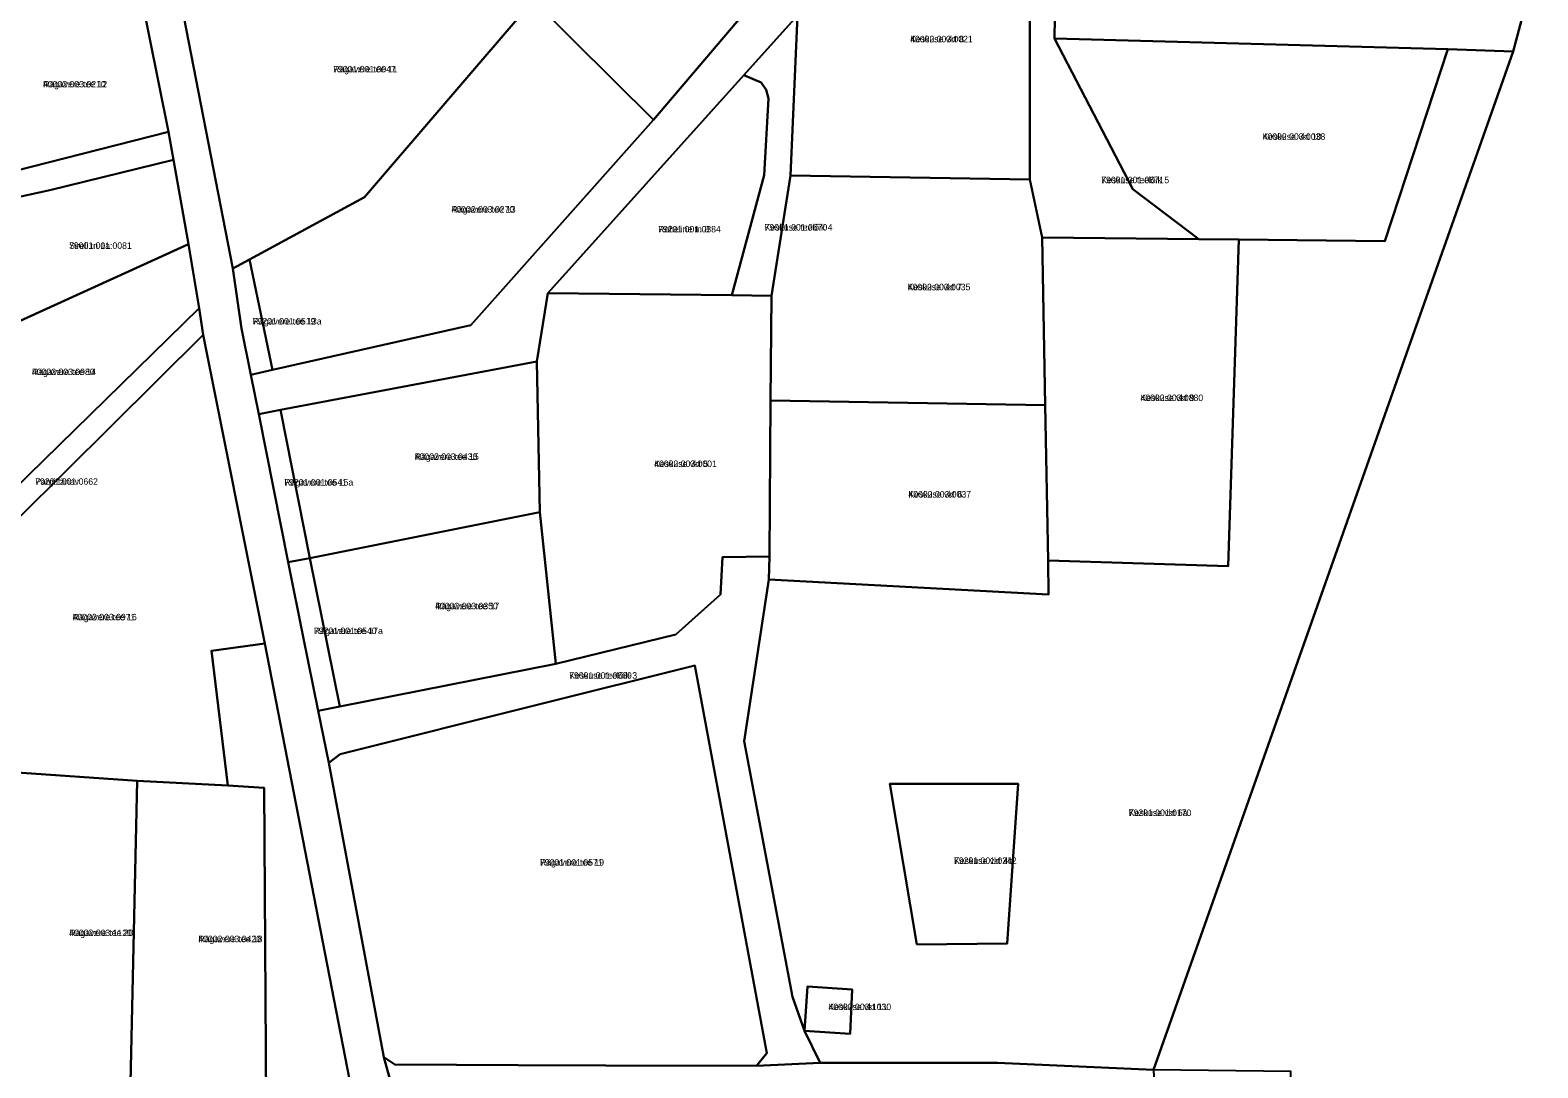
# Model space of a CAD drawing. Extents: x 587616 to 632239, y 6547421 to 6574977.
# Drawn here: x 603991.3 to 604340.3, y 6569303.6 to 6569543.9 of the extents above; entities that cross this region are included whole.
import ezdxf

# ---------------------------------------------------------------- set-up
doc = ezdxf.new("R2010")
doc.units = 0
for name, color, linetype in [('L_AADRESS', 7, 'Continuous'), ('PIIR', 7, 'Continuous'), ('TUNNUS', 7, 'Continuous')]:
    doc.layers.add(name, color=color, linetype=linetype)

msp = doc.modelspace()

# ---------------------------------------------------------------- linework, layer by layer
at = {"layer": 'PIIR'}
for points in [[(603982.29, 6569732.31), (603991.72, 6569734.34), (603999.57, 6569736.03), (603992.82, 6569727.43), (603996.82, 6569702.19), (604003.22, 6569669.18), (604004.94, 6569661.89), (604011.11, 6569629.43), (604017.79, 6569595.04), (604018.7, 6569588.68), (604025.25, 6569555.77), (604038.27, 6569488.72), (604040.3, 6569474.82), (604042.44, 6569464.1), (604044.26, 6569454.94), (604051.09, 6569420.69), (604054.53, 6569403.44), (604058.03, 6569386.3), (604060.49, 6569374.22), (604073.19, 6569306.11), (604076.71, 6569293.52)], [(604069.43, 6569279.45), (604045.67, 6569401.88), (604031.42, 6569473.35), (604030.48, 6569479.48), (604027.98, 6569494.3), (604024.51, 6569513.82), (604023.35, 6569520.32), (604016.54, 6569554.1), (604009.88, 6569586.85), (604008.39, 6569592.82), (604001.97, 6569626.48), (603995.19, 6569660.95), (603994, 6569667.82), (603987.46, 6569701.73)], [(604168.95, 6569547.25), (604156.51, 6569533.42), (604111.2, 6569483.01), (604108.65, 6569467.12), (604049.32, 6569455.96), (604044.26, 6569454.94), (604042.44, 6569464.1), (604047.45, 6569465.21), (604093.34, 6569475.55), (604135.66, 6569523.13), (604156.33, 6569547.41)]]:
    msp.add_lwpolyline(points, dxfattribs=at)
for points in [[(604256.56, 6569639.11), (604352.31, 6569665.54), (604360.92, 6569638.11), (604334.64, 6569538.95), (604319.53, 6569539.5), (604228.48, 6569541.95), (604229.44, 6569604.23), (604250.45, 6569622.25), (604254.82, 6569629.57)], [(604360.92, 6569638.11), (604431.51, 6569646.89), (604362.29, 6569373.98), (604343.36, 6569297.94), (604283.29, 6569296.75), (604283.18, 6569302.74), (604251.37, 6569303.14), (604334.64, 6569538.95)], [(604216.65, 6569593.17), (604229.44, 6569604.23), (604228.48, 6569541.95), (604234.54, 6569530.24), (604246.61, 6569507.02), (604261.9, 6569495.47), (604225.63, 6569495.88), (604222.76, 6569509.28), (604222.68, 6569588.48)], [(604216.65, 6569593.17), (604222.68, 6569588.48), (604222.76, 6569509.28), (604167.31, 6569510.23), (604168.95, 6569547.25)], [(604038.27, 6569488.72), (604025.25, 6569555.77), (604062.72, 6569563.1), (604094.43, 6569568.97), (604115.49, 6569573.57), (604129.54, 6569579.47), (604131.26, 6569576.68), (604107.75, 6569550.7), (604068.73, 6569505.19), (604042.12, 6569490.8)], [(604135.66, 6569523.13), (604107.75, 6569550.7), (604131.26, 6569576.68), (604156.33, 6569547.41)], [(603965.12, 6569543.33), (603973.78, 6569545.1), (604016.54, 6569554.1), (604023.35, 6569520.32), (603971.54, 6569507.11)], [(604042.12, 6569490.8), (604068.73, 6569505.19), (604107.75, 6569550.7), (604135.66, 6569523.13), (604093.34, 6569475.55), (604047.45, 6569465.21)], [(604156.51, 6569533.42), (604168.95, 6569547.25), (604167.31, 6569510.23), (604162.93, 6569482.38), (604153.76, 6569482.49), (604161.23, 6569510.31), (604162.22, 6569528.02), (604161.7, 6569530.08), (604160.55, 6569531.75)], [(604228.48, 6569541.95), (604319.53, 6569539.5), (604304.93, 6569495), (604271.1, 6569495.37), (604261.9, 6569495.47), (604246.61, 6569507.02), (604234.54, 6569530.24)], [(604162.33, 6569416.66), (604227.1, 6569413.22), (604226.97, 6569421.06), (604268.63, 6569419.74), (604271.1, 6569495.37), (604304.93, 6569495), (604319.53, 6569539.5), (604334.64, 6569538.95), (604251.37, 6569303.14), (604215.24, 6569304.78), (604174.21, 6569304.8), (604170.57, 6569312.18), (604167.82, 6569320.05), (604156.65, 6569379.28)], [(604161.23, 6569510.31), (604153.76, 6569482.49), (604111.2, 6569483.01), (604156.51, 6569533.42), (604160.55, 6569531.75), (604161.7, 6569530.08), (604162.22, 6569528.02)], [(603862.88, 6569483.6), (603861.57, 6569489.5), (603912.48, 6569499.04), (603920.87, 6569500.75), (603923.88, 6569499.22), (603971.54, 6569507.11), (604023.35, 6569520.32), (604024.51, 6569513.82), (603995.92, 6569506.83), (603972.91, 6569501.79), (603923.99, 6569491.28), (603913.66, 6569492.89)], [(604024.51, 6569513.82), (604027.98, 6569494.3), (603980.33, 6569472.63), (603972.91, 6569501.79), (603995.92, 6569506.83)], [(604167.31, 6569510.23), (604222.76, 6569509.28), (604225.63, 6569495.88), (604226.29, 6569457.08), (604162.69, 6569458.11), (604162.93, 6569482.38)], [(604271.1, 6569495.37), (604268.63, 6569419.74), (604226.97, 6569421.06), (604226.29, 6569457.08), (604225.63, 6569495.88), (604261.9, 6569495.47)], [(603967.48, 6569466.85), (603980.33, 6569472.63), (604027.98, 6569494.3), (604030.48, 6569479.48), (603983.65, 6569433.72)], [(604040.3, 6569474.82), (604038.27, 6569488.72), (604042.12, 6569490.8), (604047.45, 6569465.21), (604042.44, 6569464.1)], [(604162.93, 6569482.38), (604162.69, 6569458.11), (604162.52, 6569422.03), (604151.61, 6569421.88), (604151.14, 6569413.22), (604140.82, 6569403.98), (604113.03, 6569397.15), (604109.36, 6569432.26), (604108.65, 6569467.12), (604111.2, 6569483.01), (604153.76, 6569482.49)], [(604031.42, 6569473.35), (603956.71, 6569399.26), (603944.7, 6569397.73), (603938.22, 6569400.57), (603943.12, 6569404.71), (603947.64, 6569404.3), (603983.65, 6569433.72), (604030.48, 6569479.48)], [(604045.67, 6569401.88), (604033.32, 6569400.14), (604037.09, 6569368.95), (604016.12, 6569370.08), (603987.18, 6569372.04), (603987.59, 6569381.47), (603956.71, 6569399.26), (604031.42, 6569473.35)], [(604049.32, 6569455.96), (604108.65, 6569467.12), (604109.36, 6569432.26), (604056.1, 6569421.64)], [(604162.69, 6569458.11), (604226.29, 6569457.08), (604226.97, 6569421.06), (604227.1, 6569413.22), (604162.33, 6569416.66), (604162.52, 6569422.03)], [(604044.26, 6569454.94), (604049.32, 6569455.96), (604056.1, 6569421.64), (604051.09, 6569420.69)], [(604056.1, 6569421.64), (604109.36, 6569432.26), (604113.03, 6569397.15), (604062.99, 6569387.31)], [(604174.21, 6569304.8), (604159.51, 6569304.09), (604161.89, 6569307.03), (604153.05, 6569354.41), (604145.2, 6569396.79), (604109.33, 6569387.8), (604063.07, 6569376.21), (604060.49, 6569374.22), (604058.03, 6569386.3), (604062.99, 6569387.31), (604113.03, 6569397.15), (604140.82, 6569403.98), (604151.14, 6569413.22), (604151.61, 6569421.88), (604162.52, 6569422.03), (604162.33, 6569416.66), (604156.65, 6569379.28), (604167.82, 6569320.05), (604170.57, 6569312.18)], [(604051.09, 6569420.69), (604056.1, 6569421.64), (604062.99, 6569387.31), (604058.03, 6569386.3), (604054.53, 6569403.44)], [(604046.01, 6569295.5), (604045.51, 6569368.48), (604037.09, 6569368.95), (604033.32, 6569400.14), (604045.67, 6569401.88), (604069.43, 6569279.45), (604065.21, 6569279), (604050.67, 6569277.94), (604045.83, 6569283.07), (603983.91, 6569284.72), (603984.67, 6569297.56), (604014.53, 6569296.7)], [(604060.49, 6569374.22), (604063.07, 6569376.22), (604109.33, 6569387.8), (604145.2, 6569396.79), (604153.05, 6569354.41), (604161.89, 6569307.03), (604159.51, 6569304.09), (604124.58, 6569304.17), (604104.31, 6569304.25), (604075.76, 6569304.36), (604073.19, 6569306.11)], [(603985.01, 6569307.79), (603986.99, 6569364.95), (603987.18, 6569372.04), (604016.12, 6569370.08), (604014.53, 6569296.7), (603984.67, 6569297.56)], [(604016.12, 6569370.08), (604037.09, 6569368.95), (604045.51, 6569368.48), (604046.01, 6569295.5), (604014.53, 6569296.7)], [(604196.62, 6569332.15), (604217.54, 6569332.43), (604220.02, 6569369.38), (604190.37, 6569369.4)], [(604196.62, 6569332.15), (604190.37, 6569369.4), (604220.02, 6569369.38), (604217.54, 6569332.43)], [(604181.13, 6569311.51), (604170.57, 6569312.18), (604171.25, 6569322.47), (604181.65, 6569321.79)], [(604170.57, 6569312.18), (604181.13, 6569311.51), (604181.65, 6569321.79), (604171.25, 6569322.47)], [(604253.8, 6569253.12), (604244.02, 6569253), (604246.39, 6569256.14), (604244.76, 6569291.48), (604241.79, 6569295.12), (604235.71, 6569297.44), (604197.35, 6569298.13), (604185.57, 6569298.31), (604167.39, 6569298.13), (604119.65, 6569297.8), (604081.31, 6569296.76), (604076.71, 6569293.52), (604073.19, 6569306.11), (604075.76, 6569304.36), (604104.31, 6569304.25), (604124.58, 6569304.17), (604159.51, 6569304.09), (604174.21, 6569304.8), (604215.25, 6569304.78), (604251.37, 6569303.14), (604253.45, 6569259.81), (604257.68, 6569253.23)]]:
    msp.add_lwpolyline(points, close=True, dxfattribs=at)

# ---------------------------------------------------------------- texts
at = {"layer": 'L_AADRESS'}
for s, p in [('Keskuse vkt 8', (604195.04, 6569541.06)), ('Rägavere tee 11', (604061.49, 6569534.09)), ('Rägavere tee 12', (603994.33, 6569530.61)), ('Keskuse vkt 10', (604276.64, 6569518.48)), ('Keskuse teelõik 5', (604239.27, 6569508.43)), ('Rägavere tee 13', (604088.89, 6569501.63)), ('Keskuse teelõik 4', (604161.36, 6569497.47)), ('Roheline tn 8', (604136.71, 6569497.04)), ('Sireli tn 1a', (604000.35, 6569493.23)), ('Keskuse vkt 7', (604194.48, 6569483.65)), ('Rägavere tee 13a', (604042.86, 6569475.72)), ('Rägavere tee 14', (603991.76, 6569464.01)), ('Keskuse vkt 9', (604248.37, 6569458)), ('Rägavere tee 15', (604080.36, 6569444.38)), ('Keskuse vkt 5', (604135.79, 6569442.73)), ('Pargi tänav', (603992.52, 6569438.61)), ('Rägavere tee 15a', (604050.18, 6569438.43)), ('Keskuse vkt 6', (604194.64, 6569435.66)), ('Rägavere tee 16', (604001.19, 6569407.23)), ('Rägavere tee 17', (604085.09, 6569409.79)), ('Rägavere tee 17a', (604057.04, 6569404.05)), ('Keskuse teelõik 3', (604116.12, 6569393.71)), ('Keskuse vkt 6a', (604245.64, 6569361.93)), ('Keskuse vkt 4b', (604205.2, 6569350.83)), ('Rägavere tee 19', (604109.36, 6569350.44)), ('Rägavere tee 20', (604000.39, 6569334.13)), ('Rägavere tee 18', (604030.27, 6569332.71)), ('Keskuse vkt 11', (604176.15, 6569316.99))]:
    msp.add_text(s, height=1.5, dxfattribs=at).set_placement(p)
at = {"layer": 'TUNNUS'}
for s, p in [('40002:003:0021', (604195.04, 6569541.06)), ('79001:001:0047', (604061.49, 6569534.09)), ('40002:003:0210', (603994.33, 6569530.61)), ('40002:003:0038', (604276.64, 6569518.48)), ('79001:001:0671', (604239.27, 6569508.43)), ('40002:003:0270', (604088.89, 6569501.63)), ('79001:001:0670', (604161.36, 6569497.47)), ('79201:001:0384', (604136.71, 6569497.04)), ('79001:001:0081', (604000.35, 6569493.23)), ('40002:003:0035', (604194.48, 6569483.65)), ('79201:001:0519', (604042.86, 6569475.72)), ('40002:003:0980', (603991.76, 6569464.01)), ('40002:003:0880', (604248.37, 6569458)), ('40002:003:0430', (604080.36, 6569444.38)), ('40002:003:0001', (604135.79, 6569442.73)), ('79201:001:0662', (603992.52, 6569438.61)), ('79201:001:0541', (604050.18, 6569438.43)), ('40002:003:0037', (604194.64, 6569435.66)), ('40002:003:0971', (604001.19, 6569407.23)), ('40002:003:0350', (604085.09, 6569409.79)), ('79201:001:0540', (604057.04, 6569404.05)), ('79001:001:0669', (604116.12, 6569393.71)), ('79201:001:0170', (604245.64, 6569361.93)), ('79201:001:0242', (604205.2, 6569350.83)), ('79001:001:0571', (604109.36, 6569350.44)), ('40002:003:1120', (604000.39, 6569334.13)), ('40002:003:0420', (604030.27, 6569332.71)), ('40002:003:1030', (604176.15, 6569316.99))]:
    msp.add_text(s, height=1.5, dxfattribs=at).set_placement(p)

doc.saveas('drawing.dxf')
